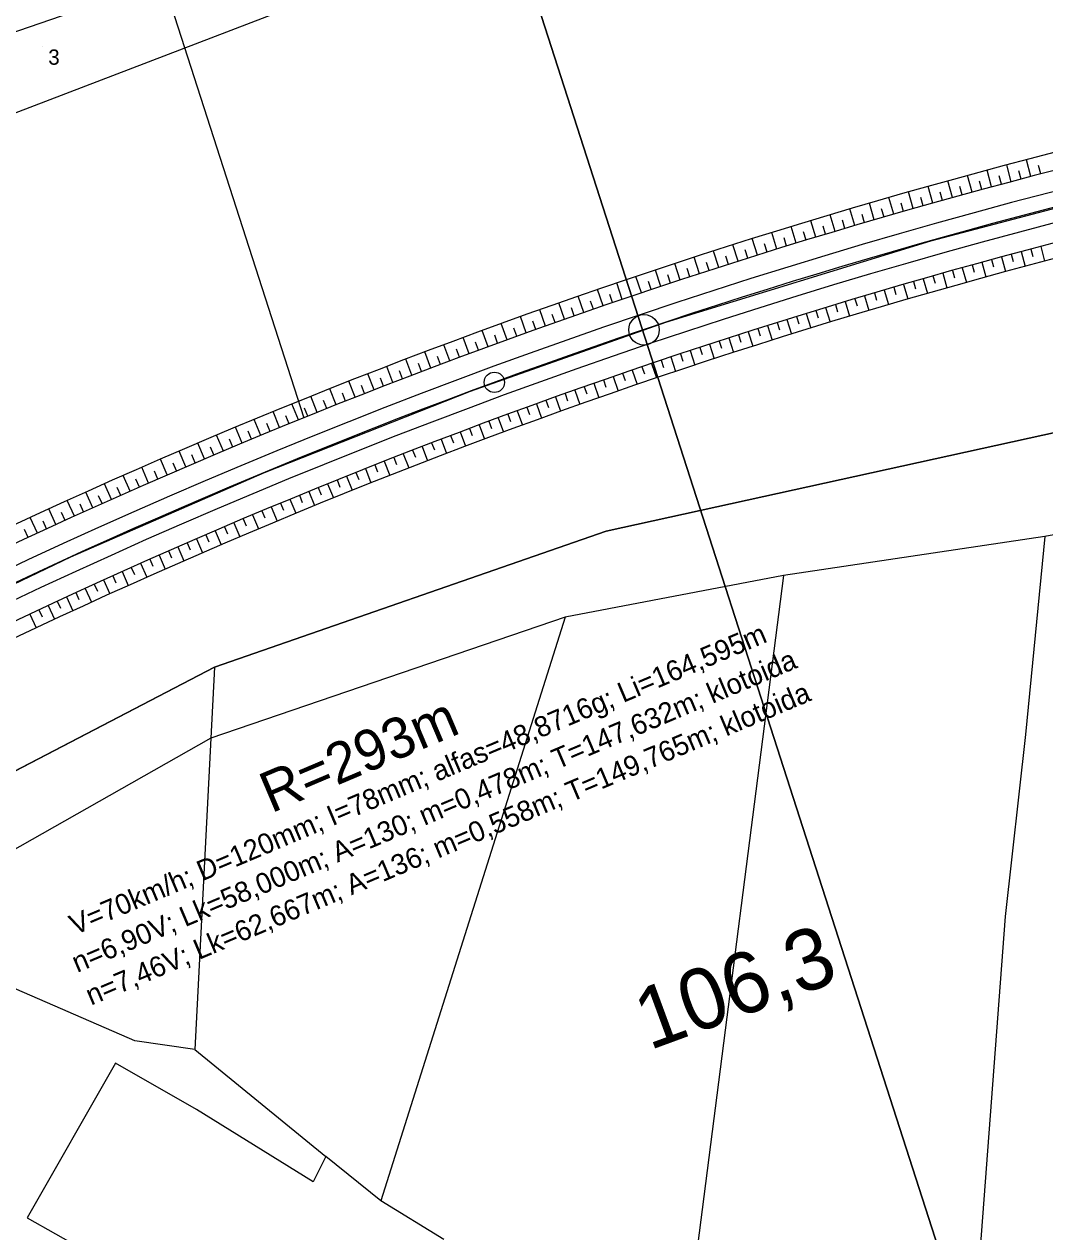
# Model space of a CAD drawing. Extents: x -758836 to -757729, y -1175316 to -1174366.
# Drawn here: x -758329.6 to -758279.4, y -1174824.7 to -1174765.3 of the extents above; entities that cross this region are included whole.
import ezdxf

# ---------------------------------------------------------------- set-up
doc = ezdxf.new("R2010")
doc.units = 0
for name, color, linetype in [('_NOR-návrh tenká', 7, 'Continuous'), ('_NOR-osa', 7, 'Continuous'), ('_NOR-pomocná', 7, 'Continuous'), ('_NOR-popis', 7, 'Continuous'), ('_NOR-svahy', 7, 'Continuous'), ('_NOR-vytyčení', 7, 'Continuous'), ('G_Obvod stavby', 7, 'Continuous'), ('Hranice parcel', 7, 'Continuous'), ('Vrstva 1', 7, 'Continuous'), ('Vrstva 7', 7, 'Continuous')]:
    doc.layers.add(name, color=color, linetype=linetype)

# ---------------------------------------------------------------- blocks, each defined once
blk = doc.blocks.new('C513_1')
at = {"layer": 'Vrstva 7'}
blk.add_circle((0, 0), 0.75, dxfattribs=at)
blk = doc.blocks.new('POINT_DISPLAY')
blk.add_line((0, 0), (0, 0))

msp = doc.modelspace()

# ---------------------------------------------------------------- linework, layer by layer
at = {"layer": '_NOR-návrh tenká'}
for radius, start, end in [(295.6, 97.09776, 129.28488), (294.75, 97.0979, 129.28474), (293.75, 97.09807, 120.96729), (292.25, 97.09832, 120.96729), (291.3, 97.09848, 129.28417), (290.55, 97.09861, 129.28404)]:
    msp.add_arc((-758205.34, -1175057.864), radius, start, end, dxfattribs=at)
at = {"layer": '_NOR-osa'}
msp.add_arc((-758205.34, -1175057.864), 293, 97.09819, 129.28445, dxfattribs=at)
at = {"layer": '_NOR-pomocná'}
for points in [[(-758317.652, -1174723.031), (-758217.708, -1174690.839), (-758172.179, -1174832.187), (-758272.123, -1174864.38)], [(-758417.595, -1174755.224), (-758317.652, -1174723.031), (-758272.123, -1174864.38), (-758372.066, -1174896.572)]]:
    msp.add_lwpolyline(points, close=True, dxfattribs=at)
at = {"layer": '_NOR-popis'}
msp.add_lwpolyline([(-758320.015, -1174740.786), (-758329.058, -1174743.698), (-758315.875, -1174784.625)], dxfattribs=at)
msp.add_circle((-758306.497, -1174782.88), 0.5, dxfattribs=at)
at = {"layer": '_NOR-svahy'}
for points in [[(-758280.099, -1174772.752), (-758280.314, -1174771.93)], [(-758282.997, -1174773.528), (-758283.221, -1174772.708)], [(-758282.032, -1174773.266), (-758282.253, -1174772.446)], [(-758281.549, -1174773.137), (-758281.659, -1174772.726)], [(-758281.066, -1174773.008), (-758281.284, -1174772.186)], [(-758280.582, -1174772.88), (-758280.691, -1174772.469)], [(-758279.615, -1174772.626), (-758279.722, -1174772.215)], [(-758284.924, -1174774.062), (-758285.154, -1174773.243)], [(-758283.961, -1174773.793), (-758284.188, -1174772.974)], [(-758283.479, -1174773.66), (-758283.592, -1174773.25)], [(-758282.514, -1174773.397), (-758282.625, -1174772.987)], [(-758286.848, -1174774.608), (-758287.083, -1174773.791)], [(-758285.887, -1174774.333), (-758286.119, -1174773.516)], [(-758285.405, -1174774.197), (-758285.521, -1174773.788)], [(-758284.443, -1174773.927), (-758284.557, -1174773.518)], [(-758288.768, -1174775.168), (-758289.009, -1174774.352)], [(-758287.809, -1174774.886), (-758288.046, -1174774.07)], [(-758287.328, -1174774.747), (-758287.447, -1174774.339)], [(-758286.367, -1174774.47), (-758286.484, -1174774.062)], [(-758290.684, -1174775.74), (-758290.931, -1174774.927)], [(-758289.727, -1174775.452), (-758289.97, -1174774.638)], [(-758289.248, -1174775.31), (-758289.369, -1174774.902)], [(-758288.289, -1174775.027), (-758288.408, -1174774.619)], [(-758292.597, -1174776.326), (-758292.848, -1174775.514)], [(-758291.641, -1174776.031), (-758291.89, -1174775.219)], [(-758291.163, -1174775.885), (-758291.287, -1174775.479)], [(-758290.206, -1174775.596), (-758290.328, -1174775.189)], [(-758294.505, -1174776.924), (-758294.762, -1174776.114)], [(-758293.551, -1174776.623), (-758293.806, -1174775.812)], [(-758293.074, -1174776.474), (-758293.201, -1174776.069)], [(-758292.119, -1174776.178), (-758292.244, -1174775.772)], [(-758280.1, -1174776.321), (-758280.004, -1174776.683)], [(-758279.617, -1174776.193), (-758279.426, -1174776.918)], [(-758296.409, -1174777.536), (-758296.672, -1174776.727)], [(-758295.458, -1174777.229), (-758295.718, -1174776.419)], [(-758294.982, -1174777.076), (-758295.111, -1174776.671)], [(-758294.028, -1174776.774), (-758294.156, -1174776.368)], [(-758282.032, -1174776.841), (-758281.933, -1174777.203)], [(-758281.549, -1174776.71), (-758281.353, -1174777.434)], [(-758281.066, -1174776.579), (-758280.969, -1174776.941)], [(-758280.584, -1174776.45), (-758280.39, -1174777.174)], [(-758298.309, -1174778.16), (-758298.577, -1174777.354)], [(-758297.36, -1174777.846), (-758297.625, -1174777.039)], [(-758296.885, -1174777.691), (-758297.017, -1174777.287)], [(-758295.934, -1174777.382), (-758296.064, -1174776.977)], [(-758284.441, -1174777.509), (-758284.237, -1174778.231)], [(-758283.959, -1174777.374), (-758283.858, -1174777.735)], [(-758283.478, -1174777.24), (-758283.277, -1174777.962)], [(-758282.996, -1174777.106), (-758282.896, -1174777.467)], [(-758282.514, -1174776.973), (-758282.315, -1174777.696)], [(-758300.205, -1174778.798), (-758300.479, -1174777.993)], [(-758299.258, -1174778.477), (-758299.529, -1174777.672)], [(-758298.784, -1174778.318), (-758298.918, -1174777.915)], [(-758297.835, -1174778.003), (-758297.968, -1174777.599)], [(-758286.364, -1174778.059), (-758286.155, -1174778.779)], [(-758285.883, -1174777.92), (-758285.78, -1174778.281)], [(-758285.403, -1174777.783), (-758285.196, -1174778.504)], [(-758284.922, -1174777.646), (-758284.819, -1174778.006)], [(-758302.097, -1174779.448), (-758302.376, -1174778.645)], [(-758301.151, -1174779.121), (-758301.428, -1174778.317)], [(-758300.678, -1174778.959), (-758300.816, -1174778.557)], [(-758299.732, -1174778.637), (-758299.868, -1174778.234)], [(-758288.283, -1174778.622), (-758288.069, -1174779.341)], [(-758287.803, -1174778.48), (-758287.697, -1174778.84)], [(-758287.324, -1174778.339), (-758287.113, -1174779.059)], [(-758286.844, -1174778.199), (-758286.739, -1174778.559)], [(-758303.983, -1174780.111), (-758304.268, -1174779.31)], [(-758303.041, -1174779.778), (-758303.322, -1174778.976)], [(-758302.569, -1174779.612), (-758302.709, -1174779.211)], [(-758301.624, -1174779.284), (-758301.763, -1174778.882)], [(-758290.198, -1174779.198), (-758289.979, -1174779.915)], [(-758289.72, -1174779.053), (-758289.611, -1174779.412)], [(-758289.241, -1174778.908), (-758289.025, -1174779.627)], [(-758288.762, -1174778.765), (-758288.655, -1174779.124)], [(-758304.925, -1174780.447), (-758305.212, -1174779.647)], [(-758304.454, -1174780.278), (-758304.597, -1174779.878)], [(-758303.512, -1174779.944), (-758303.654, -1174779.543)], [(-758292.109, -1174779.787), (-758291.886, -1174780.503)], [(-758291.632, -1174779.639), (-758291.521, -1174779.997)], [(-758291.154, -1174779.491), (-758290.933, -1174780.208)], [(-758290.676, -1174779.344), (-758290.566, -1174779.703)], [(-758306.805, -1174781.129), (-758307.098, -1174780.331)], [(-758305.866, -1174780.786), (-758306.156, -1174779.987)], [(-758305.396, -1174780.616), (-758305.54, -1174780.216)], [(-758294.016, -1174780.389), (-758293.788, -1174781.104)], [(-758293.54, -1174780.238), (-758293.426, -1174780.595)], [(-758293.063, -1174780.087), (-758292.837, -1174780.802)], [(-758292.586, -1174779.937), (-758292.474, -1174780.294)], [(-758308.681, -1174781.824), (-758308.979, -1174781.028)], [(-758307.744, -1174781.475), (-758308.039, -1174780.678)], [(-758307.275, -1174781.301), (-758307.422, -1174780.903)], [(-758306.336, -1174780.957), (-758306.481, -1174780.558)], [(-758295.919, -1174781.005), (-758295.686, -1174781.718)], [(-758295.444, -1174780.85), (-758295.328, -1174781.206)], [(-758294.968, -1174780.696), (-758294.738, -1174781.409)], [(-758294.493, -1174780.542), (-758294.378, -1174780.899)], [(-758309.617, -1174782.176), (-758309.917, -1174781.381)], [(-758309.149, -1174782), (-758309.299, -1174781.602)], [(-758308.212, -1174781.649), (-758308.361, -1174781.251)], [(-758297.818, -1174781.633), (-758297.58, -1174782.344)], [(-758297.344, -1174781.475), (-758297.225, -1174781.831)], [(-758296.869, -1174781.317), (-758296.634, -1174782.029)], [(-758296.394, -1174781.161), (-758296.277, -1174781.517)], [(-758311.485, -1174782.89), (-758311.791, -1174782.097)], [(-758310.551, -1174782.531), (-758310.855, -1174781.737)], [(-758310.084, -1174782.353), (-758310.235, -1174781.956)], [(-758299.712, -1174782.275), (-758299.469, -1174782.984)], [(-758299.239, -1174782.113), (-758299.118, -1174782.468)], [(-758298.766, -1174781.952), (-758298.525, -1174782.663)], [(-758298.292, -1174781.792), (-758298.172, -1174782.148)], [(-758313.348, -1174783.616), (-758313.66, -1174782.826)], [(-758312.417, -1174783.252), (-758312.726, -1174782.46)], [(-758311.951, -1174783.07), (-758312.105, -1174782.674)], [(-758311.018, -1174782.71), (-758311.171, -1174782.314)], [(-758301.13, -1174782.764), (-758301.007, -1174783.118)], [(-758300.658, -1174782.6), (-758300.412, -1174783.309)], [(-758300.185, -1174782.437), (-758300.063, -1174782.792)], [(-758314.278, -1174783.984), (-758314.592, -1174783.195)], [(-758313.813, -1174783.8), (-758313.97, -1174783.405)], [(-758312.883, -1174783.434), (-758313.038, -1174783.038)], [(-758303.017, -1174783.428), (-758302.891, -1174783.782)], [(-758302.546, -1174783.261), (-758302.295, -1174783.968)], [(-758302.074, -1174783.095), (-758301.95, -1174783.448)], [(-758301.602, -1174782.929), (-758301.354, -1174783.637)], [(-758316.134, -1174784.73), (-758316.453, -1174783.942)], [(-758315.207, -1174784.356), (-758315.523, -1174783.567)], [(-758314.742, -1174784.17), (-758314.9, -1174783.775)], [(-758304.429, -1174783.935), (-758304.173, -1174784.64)], [(-758303.958, -1174783.765), (-758303.831, -1174784.118)], [(-758303.488, -1174783.597), (-758303.235, -1174784.303)], [(-758317.06, -1174785.107), (-758317.382, -1174784.321)], [(-758316.597, -1174784.918), (-758316.758, -1174784.525)], [(-758315.67, -1174784.542), (-758315.83, -1174784.148)], [(-758306.307, -1174784.622), (-758306.047, -1174785.325)], [(-758305.838, -1174784.449), (-758305.708, -1174784.801)], [(-758305.368, -1174784.277), (-758305.111, -1174784.981)], [(-758304.899, -1174784.106), (-758304.77, -1174784.458)], [(-758318.908, -1174785.872), (-758319.236, -1174785.087)], [(-758317.985, -1174785.488), (-758318.31, -1174784.703)], [(-758317.522, -1174785.297), (-758317.684, -1174784.904)], [(-758307.713, -1174785.145), (-758307.581, -1174785.496)], [(-758307.244, -1174784.97), (-758306.982, -1174785.673)], [(-758306.776, -1174784.796), (-758306.645, -1174785.147)], [(-758319.83, -1174786.259), (-758320.16, -1174785.475)], [(-758319.369, -1174786.065), (-758319.534, -1174785.673)], [(-758318.447, -1174785.68), (-758318.61, -1174785.287)], [(-758309.116, -1174785.676), (-758308.848, -1174786.377)], [(-758308.648, -1174785.498), (-758308.515, -1174785.849)], [(-758308.181, -1174785.321), (-758307.916, -1174786.023)], [(-758321.671, -1174787.042), (-758322.006, -1174786.261)], [(-758320.751, -1174786.649), (-758321.084, -1174785.867)], [(-758320.291, -1174786.453), (-758320.457, -1174786.062)], [(-758310.982, -1174786.395), (-758310.71, -1174787.094)], [(-758310.516, -1174786.214), (-758310.38, -1174786.564)], [(-758310.049, -1174786.034), (-758309.78, -1174786.734)], [(-758309.583, -1174785.855), (-758309.448, -1174786.205)], [(-758322.589, -1174787.438), (-758322.927, -1174786.658)], [(-758322.13, -1174787.239), (-758322.298, -1174786.849)], [(-758321.211, -1174786.845), (-758321.378, -1174786.454)], [(-758312.378, -1174786.943), (-758312.241, -1174787.291)], [(-758311.913, -1174786.759), (-758311.639, -1174787.457)], [(-758311.448, -1174786.577), (-758311.311, -1174786.926)], [(-758324.421, -1174788.24), (-758324.764, -1174787.462)], [(-758323.506, -1174787.837), (-758323.846, -1174787.059)], [(-758323.047, -1174787.637), (-758323.217, -1174787.248)], [(-758313.772, -1174787.497), (-758313.493, -1174788.193)], [(-758313.308, -1174787.312), (-758313.169, -1174787.66)], [(-758312.843, -1174787.127), (-758312.566, -1174787.824)], [(-758325.335, -1174788.645), (-758325.681, -1174787.869)], [(-758324.878, -1174788.442), (-758325.051, -1174788.054)], [(-758323.963, -1174788.038), (-758324.134, -1174787.649)], [(-758315.163, -1174788.059), (-758315.021, -1174788.407)], [(-758314.7, -1174787.871), (-758314.418, -1174788.566)], [(-758314.236, -1174787.684), (-758314.096, -1174788.032)], [(-758327.159, -1174789.466), (-758327.51, -1174788.692)], [(-758326.248, -1174789.054), (-758326.596, -1174788.279)], [(-758325.792, -1174788.849), (-758325.965, -1174788.461)], [(-758317.013, -1174788.82), (-758316.869, -1174789.166)], [(-758316.551, -1174788.628), (-758316.264, -1174789.322)], [(-758316.088, -1174788.438), (-758315.946, -1174788.785)], [(-758315.626, -1174788.248), (-758315.342, -1174788.942)], [(-758328.069, -1174789.881), (-758328.423, -1174789.108)], [(-758327.614, -1174789.673), (-758327.79, -1174789.286)], [(-758326.704, -1174789.259), (-758326.879, -1174788.872)], [(-758318.397, -1174789.398), (-758318.105, -1174790.09)], [(-758317.936, -1174789.205), (-758317.791, -1174789.55)], [(-758317.474, -1174789.012), (-758317.186, -1174789.704)], [(-758328.977, -1174790.299), (-758329.334, -1174789.527)], [(-758328.523, -1174790.089), (-758328.701, -1174789.703)], [(-758319.777, -1174789.984), (-758319.63, -1174790.329)], [(-758319.317, -1174789.788), (-758319.024, -1174790.478)], [(-758318.857, -1174789.593), (-758318.711, -1174789.938)], [(-758329.431, -1174790.509), (-758329.61, -1174790.123)], [(-758321.155, -1174790.577), (-758320.857, -1174791.265)], [(-758320.696, -1174790.378), (-758320.548, -1174790.723)], [(-758320.237, -1174790.181), (-758319.941, -1174790.87)], [(-758322.53, -1174791.177), (-758322.379, -1174791.52)], [(-758322.072, -1174790.976), (-758321.772, -1174791.663)], [(-758321.614, -1174790.776), (-758321.464, -1174791.12)], [(-758323.902, -1174791.784), (-758323.597, -1174792.469)], [(-758323.445, -1174791.581), (-758323.293, -1174791.923)], [(-758322.988, -1174791.378), (-758322.685, -1174792.064)], [(-758324.815, -1174792.192), (-758324.507, -1174792.876)], [(-758324.358, -1174791.988), (-758324.205, -1174792.33)], [(-758326.181, -1174792.811), (-758326.025, -1174793.152)], [(-758325.726, -1174792.604), (-758325.416, -1174793.287)], [(-758325.27, -1174792.398), (-758325.116, -1174792.74)], [(-758327.544, -1174793.437), (-758327.23, -1174794.118)], [(-758327.09, -1174793.227), (-758326.933, -1174793.568)], [(-758326.636, -1174793.019), (-758326.323, -1174793.701)], [(-758328.904, -1174794.07), (-758328.745, -1174794.409)], [(-758328.451, -1174793.858), (-758328.134, -1174794.538)], [(-758327.998, -1174793.647), (-758327.84, -1174793.987)], [(-758329.357, -1174794.282), (-758329.038, -1174794.961)]]:
    msp.add_lwpolyline(points, dxfattribs=at)
at = {"layer": 'G_Obvod stavby'}
msp.add_lwpolyline([(-758392.72, -1174840.756), (-758391.23, -1174838.56), (-758368.37, -1174821.64), (-758340.31, -1174807.33), (-758320.27, -1174796.89), (-758301, -1174790.21), (-758267.96, -1174782.93), (-758224.96, -1174775.27), (-758184.87, -1174772.83), (-758142.71, -1174770.26), (-758089.84, -1174768.68), (-758106.02, -1174731.44), (-758149.09, -1174725.67), (-758199.62, -1174726.6), (-758225.76, -1174732.36), (-758252.17, -1174738.18), (-758254.97, -1174739.34), (-758266.58, -1174744.16), (-758279.45, -1174749.49), (-758302.42, -1174759.02), (-758331.68, -1174770.24), (-758367.17, -1174799.81), (-758405.64, -1174832.2)], dxfattribs=at)
at = {"layer": 'Hranice parcel'}
for p, q in [((-758333.29, -1174766.74), (-758319.98, -1174762.15)), ((-758263.72, -1174787.54), (-758279.42, -1174790.47)), ((-758279.42, -1174790.47), (-758292.27, -1174792.38)), ((-758292.27, -1174792.38), (-758303.02, -1174794.43)), ((-758292.27, -1174792.38), (-758297.37, -1174832.15)), ((-758303.02, -1174794.43), (-758320.45, -1174800.39)), ((-758303.02, -1174794.43), (-758312.09, -1174823.15)), ((-758320.27, -1174796.89), (-758340.31, -1174807.33)), ((-758320.27, -1174796.89), (-758320.45, -1174800.39)), ((-758320.45, -1174800.39), (-758336.94, -1174809.74)), ((-758320.45, -1174800.39), (-758321.24, -1174815.71)), ((-758321.24, -1174815.71), (-758314.78, -1174820.96)), ((-758312.09, -1174823.15), (-758314.78, -1174820.96)), ((-758308.98, -1174825.05), (-758312.09, -1174823.15))]:
    msp.add_line(p, q, dxfattribs=at)
for points in [[(-758279.45, -1174749.49), (-758302.42, -1174759.02), (-758331.68, -1174770.24)], [(-758184.87, -1174772.83), (-758224.96, -1174775.27), (-758267.96, -1174782.93), (-758301, -1174790.21), (-758320.27, -1174796.89)], [(-758279.42, -1174790.47), (-758280.36, -1174800.21), (-758281.37, -1174809.16), (-758283.71, -1174840.27)], [(-758321.24, -1174815.71), (-758324.19, -1174815.27), (-758336.94, -1174809.74)], [(-758314.78, -1174820.96), (-758315.41, -1174822.21), (-758321.15, -1174818.65), (-758325.13, -1174816.38), (-758329.48, -1174823.98), (-758325.3, -1174826.34), (-758323.58, -1174827.35), (-758321.82, -1174828.41), (-758323.72, -1174831.57)]]:
    msp.add_lwpolyline(points, dxfattribs=at)
at = {"layer": 'Vrstva 1'}
msp.add_lwpolyline([(-758443.817, -1174881.252), (-758441.673, -1174879.1), (-758423.412, -1174860.854), (-758412.446, -1174850.23), (-758405.322, -1174843.614), (-758399.028, -1174837.996), (-758392.64, -1174832.554), (-758380.106, -1174822.693), (-758371.773, -1174816.721), (-758363.37, -1174811.125), (-758354.46, -1174805.649), (-758345.526, -1174800.592), (-758336.614, -1174795.909), (-758327.338, -1174791.462), (-758317.813, -1174787.314), (-758307.666, -1174783.315), (-758298.059, -1174779.921), (-758285.017, -1174775.914), (-758275.047, -1174773.289)], dxfattribs=at)

# ---------------------------------------------------------------- block references
at = {"layer": '_NOR-vytyčení'}
msp.add_blockref('POINT_DISPLAY', (-758328.741, -1174766.355), dxfattribs=at)
at = {"layer": 'Vrstva 7', "rotation": 19.45750276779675}
msp.add_blockref('C513_1', (-758299.134, -1174780.301), dxfattribs=at)

# ---------------------------------------------------------------- texts
at = {"layer": '_NOR-popis'}
for s, height, rotation, p in [('V=70km/h; D=120mm; I=78mm; alfas=48,8716g; Li=164,595m', 1, 22.95999, (-758327.13, -1174810.083)), ('n=6,90V; Lk=58,000m; A=130; m=0,478m; T=147,632m; klotoida', 1, 22.95999, (-758327.02, -1174811.937)), ('n=7,46V; Lk=62,667m; A=136; m=0,558m; T=149,765m; klotoida', 1, 22.95999, (-758326.338, -1174813.548)), ('R=293m', 2, 22.95999, (-758317.473, -1174804.091)), ('106,3', 3, 20.19687, (-758298.874, -1174815.754))]:
    msp.add_text(s, height=height, rotation=rotation, dxfattribs=at).set_placement(p)
at = {"layer": '_NOR-vytyčení'}
msp.add_text('3', height=0.75, rotation=360, dxfattribs=at).set_placement((-758328.441, -1174767.255))

doc.saveas('drawing.dxf')
